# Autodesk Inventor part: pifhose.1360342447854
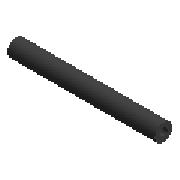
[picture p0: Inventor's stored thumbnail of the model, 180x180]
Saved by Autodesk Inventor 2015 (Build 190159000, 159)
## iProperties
IsCustomPart: 1
Company: Parker Hannifin
Created: 2011-02
Material: Rubber
Description: Tömlő
Document SubType Name: Modeling
Standard: Parker
Designer: Marci
Manufacturer: Parker
Language: hu-HU
Size Designation: 1/4 - 5
Categories: <MemberInstance><Categories><Category DisplayName="Csővezetékek" InternalName="4347fa0f-2144-441d-94cd-e3e15c92b736" Mnemonic="TUBEANDPIPE"><CategoryParameter D
Stock Number: Parker hidraulikatömlő - No Skive 1/4
Density: 1 g/cm^3
Appearance: Rubber - Black - Version 1.1
NAME: PIPING: Parker Hydraulic Hose - No Skive
DATA: <meta><inlinegroups number="1" deflen="12.7"></inlinegroups><connections number="2"></connections><angles><a>3.14159265358979</a></angles></meta>
L: 21,668 in
PL: 21,668 in
RPL: 21,750 in
OPL: 21,668 in
ROPL: 21,750 in
Author: Marci
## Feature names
1. Sweep1
## Parameters: ID = 6.35 mm, OD = 14.986 mm, L = 550.3672 mm, PL = 550.3672 mm, Size_Designation = 2.5 mm, d6 = 0, RPL = 552.45 mm, OPL = 550.3672 mm, ROPL = 552.45 mm, d7 = 0
